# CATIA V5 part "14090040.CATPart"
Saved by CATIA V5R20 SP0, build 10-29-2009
Part number: 14090040
Definition: NONE
Nomenclature: 14090040
Source: Unknown
Description: 14090040
Bounding box of the stored display mesh (mm): x -20 to 80, y -59 to 49.1, z -49.1 to 49.1
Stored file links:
  C:\Users\Utente\Desktop\IO LAVORO\3D X SITO CF\X SITO\PLASTICA\RF2\14090040.CATPart
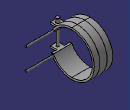
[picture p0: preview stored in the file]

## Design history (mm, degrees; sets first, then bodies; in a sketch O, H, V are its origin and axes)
Body1 "14090040" (main body)
  Solid1: solid without history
